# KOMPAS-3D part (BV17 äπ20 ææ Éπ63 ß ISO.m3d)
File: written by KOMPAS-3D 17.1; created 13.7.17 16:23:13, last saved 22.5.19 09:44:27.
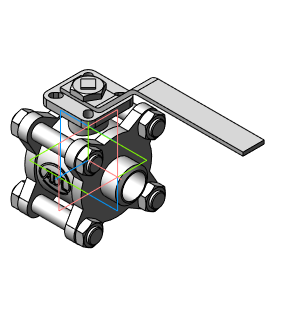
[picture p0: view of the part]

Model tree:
1. Операция без истории:1  (labels: Сталь 20  ГОСТ 1050-88)

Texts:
  DISO1
  DISO2
  BV17 Ду8 1/4" Ру63 с ISO
  BV17 Ду8 СС Ру63 с ISO
  BV17 Ду10 3/8" Ру63 с ISO
  BV17 Ду10 СС Ру63 с ISO
  BV17 Ду15 1/2" Ру63 с ISO
  BV17 Ду15 СС Ру63 с ISO
  BV17 Ду15 ФФ Ру40 с ISO
  BV17 Ду20 3/4" Ру63 с ISO
  BV17 Ду20 СС Ру40 с ISO
  BV17 Ду20 ФФ Ру40 с ISO
  BV17 Ду25 1" Ру63 с ISO
  BV17 Ду25 СС Ру63 с ISO
  BV17 Ду25 ФФ Ру40 с ISO
  BV17 Ду32 1 1/4" Ру63 с ISO
  BV17 Ду32 СС Ру63 с ISO
  BV17 Ду32 ФФ Ру40 с ISO
  BV17 Ду40 1 1/2" Ру63 с ISO
  BV17 Ду40 СС Ру63 с ISO
  BV17 Ду40 ФФ Ру40 с ISO
  BV17 Ду50 2" Ру63 с ISO
  BV17 Ду50 СС Ру63 с ISO
  BV17 Ду50 ФФ Ру40 с ISO
  BV17 Ду65 2 1/2" Ру40 с ISO
  BV17 Ду65 СС Ру40 с ISO
  BV17 Ду65 ФФ Ру40 с ISO
  BV17 Ду80 3" Ру40 с ISO
  BV17 Ду80 СС Ру40 с ISO
  BV17 Ду80 ФФ Ру40 с ISO
  BV17 Ду100 4" Ру40 с ISO
  BV17 Ду100 СС Ру40 с ISO
  BV17 Ду100 ФФ Ру40 с ISO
